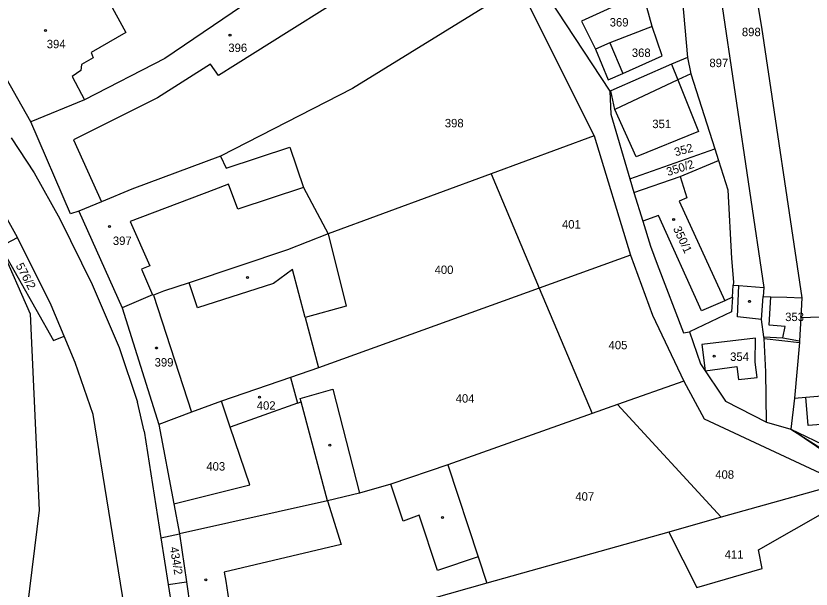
# Model space of a CAD drawing. Extents: x -563148 to -561712, y -1182311 to -1179502.
# Drawn here: x -562472.3 to -562330.8, y -1180632.4 to -1180530.4 of the extents above; entities that cross this region are included whole.
import ezdxf

# ---------------------------------------------------------------- set-up
doc = ezdxf.new("R2010")
doc.units = 0
for name, color, linetype in [('Vrstva 55', 7, 'Continuous'), ('Vrstva 56', 7, 'Continuous'), ('Vrstva 57', 7, 'Continuous')]:
    doc.layers.add(name, color=color, linetype=linetype)

msp = doc.modelspace()

# ---------------------------------------------------------------- linework, layer by layer
at = {"layer": 'Vrstva 55'}
for p, q in [((-562345.46, -1180498.35), (-562339.66, -1180532.39)), ((-562349.87, -1180506.75), (-562339.23, -1180578.72)), ((-562355.42, -1180508.51), (-562352.84, -1180537.76)), ((-562380.07, -1180523.31), (-562366.65, -1180543.76)), ((-562382.79, -1180524.99), (-562412.44, -1180543.32)), ((-562382.79, -1180524.99), (-562369.45, -1180551.74)), ((-562360.73, -1180526.3), (-562371.65, -1180531.32)), ((-562359.12, -1180532.26), (-562360.73, -1180526.3)), ((-562430.35, -1180527.42), (-562445.81, -1180537.93)), ((-562371.65, -1180531.32), (-562369.16, -1180536.29)), ((-562469.67, -1180549.2), (-562478.88, -1180532.92)), ((-562359.12, -1180532.26), (-562366.64, -1180535.17)), ((-562357.31, -1180537.49), (-562359.12, -1180532.26)), ((-562339.66, -1180532.39), (-562332.45, -1180580.54)), ((-562366.64, -1180535.17), (-562369.16, -1180536.29)), ((-562369.16, -1180536.29), (-562366.96, -1180541.74)), ((-562445.81, -1180537.93), (-562460.08, -1180545.3)), ((-562364.34, -1180540.65), (-562357.31, -1180537.49)), ((-562352.84, -1180537.76), (-562355.65, -1180538.99)), ((-562352.84, -1180537.76), (-562352.21, -1180540.68)), ((-562355.65, -1180538.99), (-562366.48, -1180543.69)), ((-562355.65, -1180538.99), (-562354.54, -1180541.76)), ((-562366.96, -1180541.74), (-562364.34, -1180540.65)), ((-562352.21, -1180540.68), (-562347.97, -1180554.03)), ((-562354.54, -1180541.76), (-562350.84, -1180550.96)), ((-562412.44, -1180543.32), (-562435.88, -1180555.3)), ((-562366.48, -1180543.69), (-562366.65, -1180543.76)), ((-562366.65, -1180543.76), (-562366.43, -1180547.86)), ((-562365.76, -1180547), (-562366.48, -1180543.69)), ((-562460.08, -1180545.3), (-562469.67, -1180549.2)), ((-562361.97, -1180555.43), (-562365.76, -1180547)), ((-562366.43, -1180547.86), (-562363.05, -1180559.39)), ((-562462.57, -1180565.58), (-562469.67, -1180549.2)), ((-562350.84, -1180550.96), (-562361.97, -1180555.43)), ((-562473.17, -1180552.04), (-562469.05, -1180558.27)), ((-562369.45, -1180551.74), (-562387.75, -1180558.48)), ((-562369.45, -1180551.74), (-562362.97, -1180572.95)), ((-562434.88, -1180557.44), (-562423.56, -1180553.7)), ((-562423.56, -1180553.7), (-562421.14, -1180560.92)), ((-562363.05, -1180559.39), (-562347.97, -1180554.03)), ((-562347.97, -1180554.03), (-562347.3, -1180556.13)), ((-562435.88, -1180555.3), (-562451.68, -1180561.22)), ((-562435.88, -1180555.3), (-562434.88, -1180557.44)), ((-562354.11, -1180558.95), (-562347.3, -1180556.13)), ((-562347.3, -1180556.13), (-562345.66, -1180561.31)), ((-562469.05, -1180558.27), (-562464.48, -1180566.47)), ((-562387.75, -1180558.48), (-562416.75, -1180569.15)), ((-562387.75, -1180558.48), (-562379.19, -1180578.81)), ((-562363.05, -1180559.39), (-562362.35, -1180561.78)), ((-562362.35, -1180561.78), (-562354.11, -1180558.95)), ((-562451.68, -1180561.22), (-562457.08, -1180563.44)), ((-562421.14, -1180560.92), (-562416.75, -1180569.15)), ((-562472.02, -1180569.78), (-562476.09, -1180562.56)), ((-562362.35, -1180561.78), (-562360.78, -1180566.87)), ((-562345.66, -1180561.31), (-562344.96, -1180573.51)), ((-562457.08, -1180563.44), (-562461.1, -1180565.11)), ((-562461.1, -1180565.11), (-562462.57, -1180565.58)), ((-562461.1, -1180565.11), (-562453.38, -1180582.31)), ((-562464.48, -1180566.47), (-562458.76, -1180578.14)), ((-562360.78, -1180566.87), (-562359.4, -1180571.34)), ((-562475.04, -1180571.41), (-562472.02, -1180569.78)), ((-562466.05, -1180581.83), (-562472.02, -1180569.78)), ((-562416.75, -1180569.15), (-562424, -1180572)), ((-562416.75, -1180569.15), (-562413.56, -1180582.02)), ((-562475.04, -1180571.41), (-562469.77, -1180583.41)), ((-562475.04, -1180571.41), (-562465.6, -1180588.15)), ((-562424, -1180572), (-562441.47, -1180577.85)), ((-562359.4, -1180571.34), (-562358.21, -1180574.57)), ((-562362.97, -1180572.95), (-562379.19, -1180578.81)), ((-562362.97, -1180572.95), (-562359.04, -1180583.59)), ((-562344.96, -1180573.51), (-562344.66, -1180577.77)), ((-562358.21, -1180574.57), (-562353.5, -1180586.79)), ((-562458.76, -1180578.14), (-562453.95, -1180589.4)), ((-562441.47, -1180577.85), (-562446.06, -1180579.34)), ((-562344.82, -1180580.44), (-562344.69, -1180578.26)), ((-562344.66, -1180577.77), (-562344.69, -1180578.26)), ((-562344.69, -1180578.26), (-562343.69, -1180578.35)), ((-562446.06, -1180579.34), (-562447.81, -1180580.05)), ((-562379.19, -1180578.81), (-562418.49, -1180593.01)), ((-562379.19, -1180578.81), (-562369.79, -1180601.13)), ((-562343.69, -1180578.35), (-562339.23, -1180578.72)), ((-562339.23, -1180578.72), (-562339.35, -1180580.28)), ((-562448, -1180580.01), (-562453.38, -1180582.31)), ((-562447.81, -1180580.05), (-562448, -1180580.01)), ((-562344.82, -1180580.44), (-562344.99, -1180583.03)), ((-562339.66, -1180584.38), (-562339.35, -1180580.28)), ((-562339.35, -1180580.28), (-562337.97, -1180580.33)), ((-562337.97, -1180580.33), (-562335.15, -1180580.44)), ((-562335.15, -1180580.44), (-562332.45, -1180580.54)), ((-562332.45, -1180580.54), (-562332.65, -1180584.04)), ((-562463.71, -1180587.38), (-562466.05, -1180581.83)), ((-562453.38, -1180582.31), (-562446.86, -1180603.05)), ((-562413.56, -1180582.02), (-562420.81, -1180584.02)), ((-562469.77, -1180583.41), (-562468.18, -1180618.34)), ((-562359.04, -1180583.59), (-562353.48, -1180595.36)), ((-562344.99, -1180583.03), (-562352.48, -1180586.59)), ((-562332.65, -1180584.04), (-562321.86, -1180583.63)), ((-562420.81, -1180584.02), (-562418.49, -1180593.01)), ((-562339.21, -1180587.46), (-562339.66, -1180584.38)), ((-562332.65, -1180584.04), (-562332.88, -1180588.16)), ((-562353.5, -1180586.79), (-562352.48, -1180586.59)), ((-562352.48, -1180586.59), (-562350.51, -1180592.28)), ((-562465.6, -1180588.15), (-562463.71, -1180587.38)), ((-562461.75, -1180592.02), (-562463.71, -1180587.38)), ((-562339.19, -1180587.76), (-562339.21, -1180587.46)), ((-562338.88, -1180593.68), (-562339.19, -1180587.76)), ((-562332.88, -1180588.16), (-562332.91, -1180588.46)), ((-562453.95, -1180589.4), (-562450.69, -1180599.08)), ((-562332.91, -1180588.46), (-562333.78, -1180598.36)), ((-562458.54, -1180601.3), (-562461.75, -1180592.02)), ((-562350.51, -1180592.28), (-562346.07, -1180598.93)), ((-562418.49, -1180593.01), (-562423.46, -1180594.7)), ((-562338.78, -1180602.64), (-562338.88, -1180593.68)), ((-562423.46, -1180594.7), (-562435.75, -1180598.89)), ((-562423.46, -1180594.7), (-562422.22, -1180599.27)), ((-562353.48, -1180595.36), (-562365.27, -1180599.53)), ((-562353.48, -1180595.36), (-562349.88, -1180602.07)), ((-562421.74, -1180598.42), (-562415.93, -1180596.81)), ((-562415.93, -1180596.81), (-562411.17, -1180615.26)), ((-562331.79, -1180598.18), (-562319.19, -1180597.24)), ((-562449.49, -1180604.23), (-562450.69, -1180599.08)), ((-562435.75, -1180598.89), (-562441.08, -1180600.89)), ((-562434.16, -1180603.57), (-562435.75, -1180598.89)), ((-562422.22, -1180599.27), (-562421.57, -1180599.04)), ((-562421.57, -1180599.04), (-562421.74, -1180598.42)), ((-562346.07, -1180598.93), (-562338.78, -1180602.64)), ((-562333.78, -1180598.36), (-562334.46, -1180603.89)), ((-562333.78, -1180598.36), (-562331.79, -1180598.18)), ((-562441.08, -1180600.89), (-562446.86, -1180603.05)), ((-562365.27, -1180599.53), (-562369.79, -1180601.13)), ((-562365.27, -1180599.53), (-562346.82, -1180619.58)), ((-562449.2, -1180658.76), (-562458.54, -1180601.3)), ((-562369.79, -1180601.13), (-562395.47, -1180610.22)), ((-562349.88, -1180602.07), (-562337.26, -1180607.92)), ((-562446.86, -1180603.05), (-562444.19, -1180617.18)), ((-562430.69, -1180613.8), (-562434.16, -1180603.57)), ((-562338.78, -1180602.64), (-562334.46, -1180603.89)), ((-562449.49, -1180604.23), (-562446.53, -1180623.22)), ((-562334.46, -1180603.89), (-562320.21, -1180612.96)), ((-562337.26, -1180607.92), (-562325.35, -1180613.54)), ((-562395.47, -1180610.22), (-562405.61, -1180613.68)), ((-562395.47, -1180610.22), (-562390.08, -1180626.59)), ((-562325.35, -1180613.54), (-562346.82, -1180619.58)), ((-562444.19, -1180617.18), (-562430.69, -1180613.8)), ((-562405.61, -1180613.68), (-562411.17, -1180615.26)), ((-562411.17, -1180615.26), (-562416.85, -1180616.67)), ((-562340.2, -1180625.39), (-562323.39, -1180615.76)), ((-562444.19, -1180617.18), (-562443.18, -1180622.55)), ((-562416.85, -1180616.67), (-562443.18, -1180622.55)), ((-562468.18, -1180618.34), (-562474.01, -1180666.19)), ((-562346.82, -1180619.58), (-562356.15, -1180622.21)), ((-562446.53, -1180623.22), (-562443.18, -1180622.55)), ((-562446.53, -1180623.22), (-562445.23, -1180631.54)), ((-562443.18, -1180622.55), (-562441.95, -1180631.04)), ((-562356.15, -1180622.21), (-562388.53, -1180631.32)), ((-562356.15, -1180622.21), (-562351.13, -1180632.06)), ((-562339.52, -1180628.68), (-562340.2, -1180625.39)), ((-562390.08, -1180626.59), (-562388.53, -1180631.32)), ((-562351.13, -1180632.06), (-562339.52, -1180628.68)), ((-562445.23, -1180631.54), (-562441.95, -1180631.04)), ((-562445.23, -1180631.54), (-562442.85, -1180646.84)), ((-562441.95, -1180631.04), (-562439.97, -1180644.72)), ((-562388.53, -1180631.32), (-562398.39, -1180634.09))]:
    msp.add_line(p, q, dxfattribs=at)
at = {"layer": 'Vrstva 56'}
for p, q in [((-562455.87, -1180527.5), (-562452.77, -1180533.35)), ((-562416.85, -1180528.81), (-562423.69, -1180533.09)), ((-562452.77, -1180533.35), (-562458.94, -1180536.89)), ((-562423.69, -1180533.09), (-562433.24, -1180539.08)), ((-562366.64, -1180535.17), (-562364.34, -1180540.65)), ((-562458.94, -1180536.89), (-562458.58, -1180537.81)), ((-562458.58, -1180537.81), (-562460.66, -1180539)), ((-562460.66, -1180539), (-562460.77, -1180540.08)), ((-562437.68, -1180538.96), (-562447.12, -1180544.94)), ((-562436.24, -1180541), (-562437.68, -1180538.96)), ((-562433.24, -1180539.08), (-562436.24, -1180541)), ((-562460.77, -1180540.08), (-562462.27, -1180541.16)), ((-562462.27, -1180541.16), (-562460.08, -1180545.3)), ((-562352.21, -1180540.68), (-562354.54, -1180541.76)), ((-562354.54, -1180541.76), (-562365.76, -1180547)), ((-562447.12, -1180544.94), (-562462.03, -1180552.44)), ((-562462.03, -1180552.44), (-562457.08, -1180563.44)), ((-562354.11, -1180558.95), (-562352.96, -1180562.72)), ((-562434.47, -1180560.31), (-562437.11, -1180561.31)), ((-562432.84, -1180564.76), (-562434.47, -1180560.31)), ((-562421.14, -1180560.92), (-562432.84, -1180564.76)), ((-562437.11, -1180561.31), (-562451.95, -1180566.93)), ((-562352.96, -1180562.72), (-562354.31, -1180563.34)), ((-562354.31, -1180563.34), (-562346.18, -1180581.04)), ((-562451.95, -1180566.93), (-562448.49, -1180574.82)), ((-562357.97, -1180565.89), (-562360.78, -1180566.87)), ((-562350.31, -1180582.86), (-562357.97, -1180565.89)), ((-562448.49, -1180574.82), (-562449.93, -1180575.43)), ((-562449.93, -1180575.43), (-562448, -1180580.01)), ((-562423.08, -1180575.52), (-562426.45, -1180577.98)), ((-562420.81, -1180584.02), (-562423.08, -1180575.52)), ((-562440, -1180582.31), (-562441.47, -1180577.85)), ((-562426.45, -1180577.98), (-562440, -1180582.31)), ((-562343.92, -1180583.92), (-562343.69, -1180578.35)), ((-562447.81, -1180580.05), (-562441.08, -1180600.89)), ((-562346.18, -1180581.04), (-562350.31, -1180582.86)), ((-562344.82, -1180580.44), (-562346.18, -1180581.04)), ((-562338.28, -1180585.37), (-562337.97, -1180580.33)), ((-562339.66, -1180584.38), (-562343.92, -1180583.92)), ((-562335.46, -1180585.61), (-562338.28, -1180585.37)), ((-562335.84, -1180587.67), (-562335.46, -1180585.61)), ((-562340.71, -1180587.69), (-562350.28, -1180588.84)), ((-562340.77, -1180591.98), (-562340.71, -1180587.69)), ((-562339.21, -1180587.46), (-562335.84, -1180587.67)), ((-562339.19, -1180587.76), (-562332.91, -1180588.46)), ((-562335.84, -1180587.67), (-562332.88, -1180588.16)), ((-562350.28, -1180588.84), (-562349.69, -1180593.5)), ((-562340.45, -1180594.73), (-562340.77, -1180591.98)), ((-562349.69, -1180593.5), (-562344.05, -1180592.76)), ((-562344.05, -1180592.76), (-562343.75, -1180595.05)), ((-562343.75, -1180595.05), (-562340.45, -1180594.73)), ((-562422.22, -1180599.27), (-562434.16, -1180603.57)), ((-562416.85, -1180616.67), (-562421.57, -1180599.04)), ((-562331.35, -1180603.24), (-562331.79, -1180598.18)), ((-562322.67, -1180602.61), (-562331.35, -1180603.24)), ((-562334.46, -1180603.89), (-562320.5, -1180610.64)), ((-562323.27, -1180611.48), (-562334.46, -1180603.89)), ((-562403.4, -1180620.24), (-562405.61, -1180613.68)), ((-562416.85, -1180616.67), (-562414.43, -1180624.43)), ((-562400.57, -1180619.21), (-562403.4, -1180620.24)), ((-562397.3, -1180629.05), (-562400.57, -1180619.21)), ((-562414.43, -1180624.43), (-562435.24, -1180629.32)), ((-562390.08, -1180626.59), (-562397.3, -1180629.05)), ((-562435.24, -1180629.32), (-562434.98, -1180630.97)), ((-562434.98, -1180630.97), (-562433.09, -1180643))]:
    msp.add_line(p, q, dxfattribs=at)
at = {"layer": 'Vrstva 57'}
for centre in [(-562467.03, -1180532.96), (-562434.21, -1180533.82), (-562355.28, -1180566.62), (-562455.63, -1180567.86), (-562431.11, -1180576.92), (-562341.79, -1180581.16), (-562447.29, -1180589.46), (-562348.06, -1180590.93), (-562428.96, -1180598.19), (-562416.43, -1180606.75), (-562396.39, -1180619.64), (-562438.51, -1180630.73)]:
    msp.add_circle(centre, 0.175, dxfattribs=at)

# ---------------------------------------------------------------- texts
for s, p in [('369', (-562366.66, -1180532.26)), ('898', (-562343.14, -1180533.98)), ('394', (-562466.81, -1180536.13)), ('396', (-562434.51, -1180536.8)), ('368', (-562362.72, -1180537.68)), ('897', (-562348.92, -1180539.49)), ('398', (-562395.99, -1180550.2)), ('351', (-562359.08, -1180550.34)), ('401', (-562375.15, -1180568.2)), ('397', (-562455.05, -1180571.13)), ('400', (-562397.81, -1180576.29)), ('353', (-562335.44, -1180584.67)), ('405', (-562366.86, -1180589.69)), ('354', (-562345.23, -1180591.76)), ('399', (-562447.62, -1180592.76)), ('404', (-562394.06, -1180599.18)), ('402', (-562429.45, -1180600.44)), ('403', (-562438.42, -1180611.27)), ('408', (-562347.88, -1180612.72)), ('407', (-562372.77, -1180616.62)), ('411', (-562346.2, -1180626.95))]:
    msp.add_text(s, height=1.5, dxfattribs=at).set_placement(p)
for s, rotation, p in [('352', 15.3703, (-562354.93, -1180555.37)), ('350/2', 17.5009, (-562356.3, -1180558.88)), ('350/1', 294.9797, (-562355.42, -1180568.21)), ('576/2', 298.3284, (-562472.38, -1180574.81)), ('434/2', 279.5913, (-562444.92, -1180624.96))]:
    msp.add_text(s, height=1.5, rotation=rotation, dxfattribs=at).set_placement(p)

doc.saveas('drawing.dxf')
